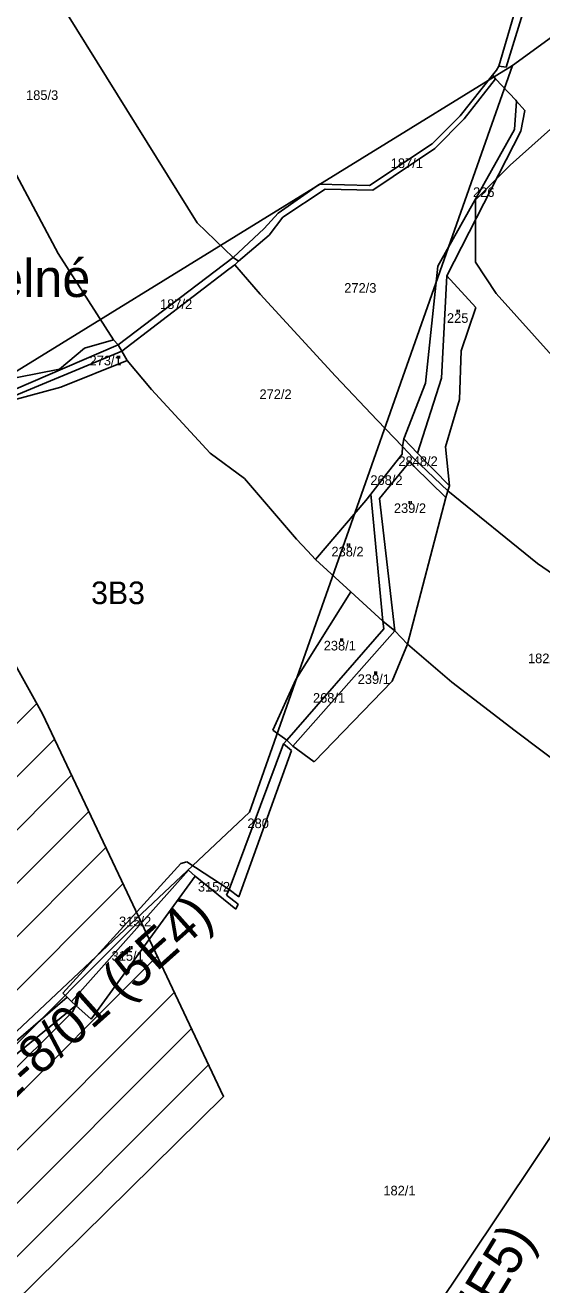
# Model space of a CAD drawing. Extents: x -564810 to -550519, y -1045831 to -1034011.
# Drawn here: x -553909 to -553635, y -1036121 to -1035452 of the extents above; entities that cross this region are included whole.
import ezdxf

# ---------------------------------------------------------------- set-up
doc = ezdxf.new("R2010")
doc.units = 0
for name, color, linetype in [('KN stav', 7, 'Continuous'), ('Odvodněné plochy', 7, 'Continuous'), ('Parcelní čísla', 7, 'Continuous'), ('STG', 7, 'Continuous'), ('Vrstva 12', 7, 'Continuous'), ('Vrstva 13', 7, 'Continuous'), ('zamokř ploch', 7, 'Continuous')]:
    doc.layers.add(name, color=color, linetype=linetype)

msp = doc.modelspace()

# ---------------------------------------------------------------- linework, layer by layer
at = {"layer": 'KN stav'}
for p, q in [((-553632.12, -1035385.31), (-553657.9, -1035474.02)), ((-553654, -1035474.49), (-553628.02, -1035389.8)), ((-553895.72, -1035432.24), (-553818.07, -1035557.12)), ((-553891.75, -1035573.45), (-553959.44, -1035446.41)), ((-553661.37, -1035478.84), (-553678.52, -1035500.39)), ((-553659.23, -1035476.15), (-553661.37, -1035478.84)), ((-553661.37, -1035478.84), (-553659.76, -1035480.72)), ((-553657.9, -1035474.02), (-553659.23, -1035476.15)), ((-553657.9, -1035474.02), (-553654, -1035474.49)), ((-553659.76, -1035480.72), (-553676.35, -1035501.99)), ((-553659.76, -1035480.72), (-553648.93, -1035492.1)), ((-553648.51, -1035492.56), (-553649.67, -1035507.56)), ((-553648.93, -1035492.1), (-553648.51, -1035492.56)), ((-553648.51, -1035492.56), (-553644.1, -1035497.48)), ((-553678.52, -1035500.39), (-553693.33, -1035515.24)), ((-553644.1, -1035497.48), (-553646.31, -1035508.53)), ((-553676.35, -1035501.99), (-553691.82, -1035517.66)), ((-553649.67, -1035507.56), (-553690.34, -1035580.07)), ((-553646.31, -1035508.53), (-553685.56, -1035585.3)), ((-553693.33, -1035515.24), (-553726.66, -1035537.29)), ((-553691.82, -1035517.66), (-553724.87, -1035539.82)), ((-553753.02, -1035536.5), (-553775.11, -1035552.04)), ((-553750.18, -1035539.25), (-553772.58, -1035554.13)), ((-553726.66, -1035537.29), (-553753.02, -1035536.5)), ((-553724.87, -1035539.82), (-553750.18, -1035539.25)), ((-553775.11, -1035552.04), (-553782.4, -1035560.19)), ((-553772.58, -1035554.13), (-553779.79, -1035563.7)), ((-553818.07, -1035557.12), (-553798.94, -1035575.5)), ((-553782.4, -1035560.19), (-553798.94, -1035575.5)), ((-553779.79, -1035563.7), (-553796.06, -1035577.39)), ((-553862.44, -1035619.14), (-553891.75, -1035573.45)), ((-553798.94, -1035575.5), (-553859.95, -1035621.79)), ((-553798.02, -1035579.3), (-553801.26, -1035581.69)), ((-553798.94, -1035575.5), (-553796.06, -1035577.39)), ((-553796.06, -1035577.39), (-553798.02, -1035579.3)), ((-553798.02, -1035579.3), (-553784.52, -1035594.89)), ((-553690.34, -1035580.07), (-553696.81, -1035642.09)), ((-553801.26, -1035581.69), (-553858.07, -1035625.23)), ((-553688.28, -1035639.45), (-553685.56, -1035585.3)), ((-553685.56, -1035585.3), (-553670.16, -1035602.05)), ((-553784.52, -1035594.89), (-553744.65, -1035638.47)), ((-553670.16, -1035602.05), (-553677.98, -1035624.94)), ((-553877.78, -1035623.6), (-553862.44, -1035619.14)), ((-553859.95, -1035621.79), (-553862.44, -1035619.14)), ((-553859.95, -1035621.79), (-553930.26, -1035652.06)), ((-553928.98, -1035654.68), (-553858.07, -1035625.23)), ((-553891.12, -1035634.76), (-553877.78, -1035623.6)), ((-553858.07, -1035625.23), (-553859.95, -1035621.79)), ((-553858.07, -1035625.23), (-553855.14, -1035630.22)), ((-553677.98, -1035624.94), (-553678.9, -1035650.77)), ((-553855.14, -1035630.22), (-553890.34, -1035644.35)), ((-553842.24, -1035645.51), (-553855.14, -1035630.22)), ((-553934.83, -1035643.22), (-553891.12, -1035634.76)), ((-553744.65, -1035638.47), (-553722.42, -1035661.72)), ((-553701.12, -1035679.36), (-553688.28, -1035639.45)), ((-553890.34, -1035644.35), (-553928.98, -1035654.68)), ((-553811.16, -1035679.31), (-553842.24, -1035645.51)), ((-553696.81, -1035642.09), (-553708.32, -1035671.74)), ((-553678.9, -1035650.77), (-553686.28, -1035676)), ((-553722.42, -1035661.72), (-553708.98, -1035675.79)), ((-553708.32, -1035671.74), (-553708.98, -1035675.79)), ((-553708.32, -1035671.74), (-553701.12, -1035679.36)), ((-553792.97, -1035692.84), (-553811.16, -1035679.31)), ((-553709.26, -1035679.92), (-553719.06, -1035692.42)), ((-553708.98, -1035675.79), (-553709.26, -1035679.92)), ((-553708.98, -1035675.79), (-553703.41, -1035681.81)), ((-553684.11, -1035696.7), (-553701.12, -1035679.36)), ((-553686.28, -1035676), (-553684.11, -1035696.7)), ((-553705.22, -1035683.74), (-553721.22, -1035703.42)), ((-553702.89, -1035686.4), (-553705.22, -1035683.74)), ((-553703.41, -1035681.81), (-553684.94, -1035699.37)), ((-553686.03, -1035702.86), (-553702.89, -1035686.4)), ((-553765.36, -1035725.01), (-553792.97, -1035692.84)), ((-553719.06, -1035692.42), (-553725.87, -1035701.1)), ((-553725.87, -1035701.1), (-553728.44, -1035704.39)), ((-553725.87, -1035701.1), (-553719.51, -1035768.4)), ((-553684.94, -1035699.37), (-553686.03, -1035702.86)), ((-553684.11, -1035696.7), (-553684.94, -1035699.37)), ((-553684.94, -1035699.37), (-553637.36, -1035737.89)), ((-553728.44, -1035704.39), (-553755.28, -1035735.75)), ((-553721.22, -1035703.42), (-553713.16, -1035773.58)), ((-553686.03, -1035702.86), (-553706.48, -1035780.62)), ((-553759.56, -1035731.2), (-553765.36, -1035725.01)), ((-553755.28, -1035735.75), (-553759.56, -1035731.2)), ((-553736.55, -1035752.84), (-553755.28, -1035735.75)), ((-553637.36, -1035737.89), (-553593.1, -1035768.58)), ((-553765.69, -1035799.4), (-553736.55, -1035752.84)), ((-553736.55, -1035752.84), (-553719.51, -1035768.4)), ((-553718.91, -1035772.55), (-553770.43, -1035831.53)), ((-553713.16, -1035773.58), (-553767.2, -1035834.74)), ((-553719.51, -1035768.4), (-553718.91, -1035772.55)), ((-553719.51, -1035768.4), (-553713.16, -1035773.58)), ((-553713.16, -1035773.58), (-553706.48, -1035780.62)), ((-553706.48, -1035780.62), (-553714.46, -1035800.21)), ((-553682.88, -1035800.89), (-553706.48, -1035780.62)), ((-553777.86, -1035826.34), (-553765.69, -1035799.4)), ((-553714.46, -1035800.21), (-553755.9, -1035843)), ((-553649.24, -1035826.56), (-553682.88, -1035800.89)), ((-553770.43, -1035831.53), (-553777.86, -1035826.34)), ((-553604.4, -1035860.46), (-553649.24, -1035826.56)), ((-553801.12, -1035910.85), (-553772.14, -1035833.49)), ((-553770.43, -1035831.53), (-553772.14, -1035833.49)), ((-553772.14, -1035833.49), (-553768.03, -1035837.03)), ((-553767.2, -1035834.74), (-553770.43, -1035831.53)), ((-553755.9, -1035843), (-553767.2, -1035834.74)), ((-553768.03, -1035837.03), (-553795.92, -1035914.74)), ((-553889.27, -1035965.8), (-553826.74, -1035897.02)), ((-553822.7, -1035900.54), (-553884.69, -1035970.2)), ((-553826.74, -1035897.02), (-553823.44, -1035896.21)), ((-553823.44, -1035896.21), (-553801.12, -1035910.85)), ((-553822.7, -1035900.54), (-553819.05, -1035903.67)), ((-553819.05, -1035903.67), (-553874.34, -1035979.7)), ((-553797.5, -1035921.19), (-553819.05, -1035903.67)), ((-553801.12, -1035910.85), (-553802.44, -1035913.85)), ((-553802.44, -1035913.85), (-553796.29, -1035918.61)), ((-553795.92, -1035914.74), (-553801.12, -1035910.85)), ((-553796.29, -1035918.61), (-553797.5, -1035921.19)), ((-553932.2, -1036006.74), (-553887.08, -1035967.94)), ((-553887.08, -1035967.94), (-553889.27, -1035965.8)), ((-553884.69, -1035970.2), (-553887.08, -1035967.94)), ((-553952.45, -1036029.43), (-553882.34, -1035972.44)), ((-553882.34, -1035972.44), (-553884.69, -1035970.2)), ((-553882.34, -1035972.44), (-553884.19, -1035975.75)), ((-553874.34, -1035979.7), (-553882.34, -1035972.44)), ((-553884.19, -1035975.75), (-553946.13, -1036037.2))]:
    msp.add_line(p, q, dxfattribs=at)
at = {"layer": 'Odvodněné plochy'}
for p, q in [((-554077.36, -1035986.34), (-553903.12, -1035812.1)), ((-554064.74, -1036002.01), (-553893.72, -1035830.99)), ((-554052.13, -1036017.68), (-553884.64, -1035850.19)), ((-554039.51, -1036033.35), (-553875.55, -1035869.39)), ((-554026.9, -1036049.02), (-553866.47, -1035888.59)), ((-554014.28, -1036064.69), (-553857.39, -1035907.8)), ((-554001.67, -1036080.36), (-553848.31, -1035927)), ((-553989.05, -1036096.03), (-553839.23, -1035946.2)), ((-553976.44, -1036111.7), (-553830.15, -1035965.41)), ((-553963.82, -1036127.37), (-553821.06, -1035984.61)), ((-553951.21, -1036143.03), (-553811.98, -1036003.81))]:
    msp.add_line(p, q, dxfattribs=at)
msp.add_lwpolyline([(-553941.08, -1036155.62), (-553804.02, -1036020.64), (-553859.83, -1035902.63), (-553900.05, -1035817.59), (-553962.27, -1035706.18), (-554082.37, -1035458.07), (-554311.27, -1035501.88), (-554358.24, -1035530.17), (-554290.96, -1035721.02)], close=True, dxfattribs=at)
at = {"layer": 'STG'}
msp.add_lwpolyline([(-553628.13, -1035629.45), (-553659.36, -1035594.54), (-553670.38, -1035578), (-553670.38, -1035544.92), (-553652.01, -1035526.55), (-553618.94, -1035497.15)], dxfattribs=at)
at = {"layer": 'Vrstva 12'}
msp.add_line((-553806.87, -1036306), (-553551.06, -1035923.11), dxfattribs=at)
for points in [[(-553490.55, -1035357.15), (-553650.74, -1035473.71)], [(-554209.3, -1035817.86), (-553650.74, -1035473.71), (-553790.3, -1035869.73), (-554007.46, -1036074.06)]]:
    msp.add_lwpolyline(points, dxfattribs=at)
at = {"layer": 'zamokř ploch'}
for p, q in [((-553679.98, -1035603.19), (-553679.98, -1035604.69)), ((-553678.98, -1035603.19), (-553678.98, -1035604.69)), ((-553860.26, -1035627.67), (-553860.26, -1035629.17)), ((-553859.26, -1035627.67), (-553859.26, -1035629.17)), ((-553705.44, -1035704.72), (-553705.44, -1035706.22)), ((-553704.44, -1035704.72), (-553704.44, -1035706.22)), ((-553738.21, -1035727.32), (-553738.21, -1035728.82)), ((-553737.21, -1035727.32), (-553737.21, -1035728.82)), ((-553741.84, -1035777.61), (-553741.84, -1035779.11)), ((-553740.84, -1035777.61), (-553740.84, -1035779.11)), ((-553723.8, -1035795.11), (-553723.8, -1035796.61)), ((-553722.8, -1035795.11), (-553722.8, -1035796.61)), ((-553853.74, -1035940.93), (-553853.74, -1035942.43)), ((-553852.74, -1035940.93), (-553852.74, -1035942.43))]:
    msp.add_line(p, q, dxfattribs=at)

# ---------------------------------------------------------------- texts
at = {"layer": 'Parcelní čísla'}
for s, p in [('185/3', (-553908.83, -1035491.88)), ('187/2', (-553837.74, -1035602.77)), ('225', (-553685.47, -1035610.16)), ('273/1', (-553875.15, -1035632.72)), ('272/2', (-553784.96, -1035650.56)), ('268/2', (-553726.13, -1035696.14)), ('239/2', (-553713.63, -1035711.04)), ('238/2', (-553746.76, -1035734.07)), ('238/1', (-553750.88, -1035783.98)), ('182/5', (-553642.47, -1035790.73)), ('239/1', (-553732.84, -1035801.74)), ('268/1', (-553756.58, -1035811.71)), ('280', (-553791.35, -1035878.24)), ('315/2', (-553859.5, -1035930.3)), ('315/1', (-553863.48, -1035948.61))]:
    msp.add_text(s, height=5.1, rotation=359.91379, dxfattribs=at).set_placement(p)
for s, height, p in [('187/1', 5.1, (-553715.3, -1035528.01)), ('226', 5.1, (-553671.63, -1035543.38)), ('K Uhelné', 20, (-553984.71, -1035596.45)), ('272/3', 5.1, (-553739.97, -1035594.2)), ('2848/2', 5.1, (-553711.22, -1035686.15)), ('315/2', 5.1, (-553817.64, -1035911.9)), ('182/1', 5.1, (-553719.21, -1036073.11))]:
    msp.add_text(s, height=height, dxfattribs=at).set_placement(p)
at = {"layer": 'STG'}
msp.add_text('3B3', height=12, dxfattribs=at).set_placement((-553874.3, -1035759.41))
at = {"layer": 'Vrstva 13'}
for s, rotation, p in [('1-132-8/01 (5E4)', 41.78892, (-553959.31, -1036061.7)), ('1-132-9/03 (5E5)', 58.59275, (-553743.56, -1036269.05))]:
    msp.add_text(s, height=20, rotation=rotation, dxfattribs=at).set_placement(p)

doc.saveas('drawing.dxf')
